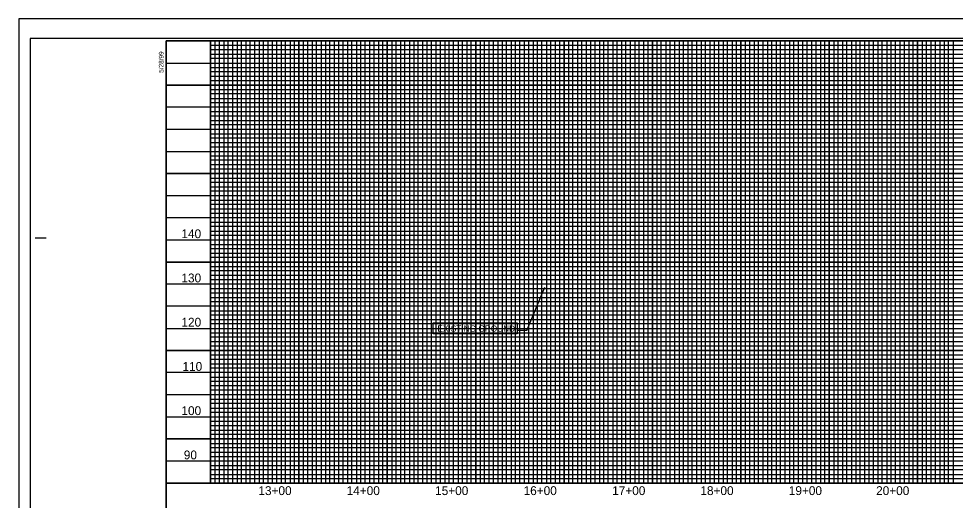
# Model space of a CAD drawing. Extents: x 10070 to 15319, y 8517 to 10343.
# Drawn here: x 13208 to 14267, y 9072 to 9617 of the extents above; entities that cross this region are included whole.
import ezdxf

# ---------------------------------------------------------------- set-up
doc = ezdxf.new("R2010")
doc.units = 0
for name, color, linetype in [('Exist Vertical Profile Horizontal Axis Label Major', 7, 'Continuous'), ('Exist Vertical Profile Vertical Axis Label', 7, 'Continuous'), ('Prop Grid Mask', 7, 'Continuous'), ('Prop VPI Label', 7, 'Continuous'), ('Scratch_Level_3', 7, 'Continuous'), ('Scratch_Level_4', 7, 'Continuous'), ('Sheet Cutting Line CELL', 7, 'Continuous'), ('Sheet DOT Grid CELL', 7, 'Continuous'), ('Sheet Layout Profile Border Port 1', 7, 'Continuous'), ('Sheet Plot Border Inside CELL', 7, 'Continuous'), ('Sheet Plot Border Outside CELL', 7, 'Continuous'), ('Sheet Profile CELL', 7, 'Continuous'), ('Sheet Profile Grid Major CELL', 7, 'Continuous'), ('Sheet Profile Grid Middle CELL', 7, 'Continuous'), ('Sheet Profile Grid Minor CELL', 7, 'Continuous')]:
    doc.layers.add(name, color=color, linetype=linetype)

msp = doc.modelspace()

# ---------------------------------------------------------------- linework, layer by layer
at = {"layer": 'Prop Grid Mask'}
msp.add_lwpolyline([(13676.8, 9260.7), (13676.8, 9272.9), (13772, 9272.9), (13772, 9260.7)], close=True, dxfattribs=at)
at = {"layer": 'Prop VPI Label'}
for q in [(13803.2, 9313.4), (13772, 9264.5)]:
    msp.add_line((13782.6, 9264.5), q, dxfattribs=at)
at = {"layer": 'Scratch_Level_3'}
msp.add_lwpolyline([(13374.9, 9591.7), (14824.9, 9591.7), (14824.9, 8566.7), (13374.9, 8566.7)], close=True, dxfattribs=at)
at = {"layer": 'Scratch_Level_4'}
msp.add_lwpolyline([(13374.9, 9591.7), (14874.9, 9591.7), (14874.9, 9091.7), (13374.9, 9091.7)], close=True, dxfattribs=at)
at = {"layer": 'Sheet Cutting Line CELL'}
for p, q in [((14891.9, 9616.7), (13207.9, 9616.7)), ((13207.9, 9616.7), (13207.9, 8516.7))]:
    msp.add_line(p, q, dxfattribs=at)
at = {"layer": 'Sheet DOT Grid CELL'}
for p, q in [((13424.9, 9091.7), (13424.9, 9591.7)), ((13474.9, 9091.7), (13474.9, 9591.7)), ((13524.9, 9091.7), (13524.9, 9591.7)), ((13574.9, 9091.7), (13574.9, 9591.7)), ((13624.9, 9091.7), (13624.9, 9591.7)), ((13674.9, 9091.7), (13674.9, 9591.7)), ((13724.9, 9091.7), (13724.9, 9591.7)), ((13774.9, 9091.7), (13774.9, 9591.7)), ((13824.9, 9091.7), (13824.9, 9591.7)), ((13874.9, 9091.7), (13874.9, 9591.7)), ((13924.9, 9091.7), (13924.9, 9591.7)), ((13974.9, 9091.7), (13974.9, 9591.7)), ((14024.9, 9091.7), (14024.9, 9591.7)), ((14074.9, 9091.7), (14074.9, 9591.7)), ((14124.9, 9091.7), (14124.9, 9591.7)), ((14174.9, 9091.7), (14174.9, 9591.7)), ((14224.9, 9091.7), (14224.9, 9591.7)), ((14674.9, 9541.7), (13374.9, 9541.7)), ((14674.9, 9491.7), (13374.9, 9491.7)), ((14674.9, 9441.7), (13374.9, 9441.7)), ((14874.9, 9391.7), (13374.9, 9391.7)), ((14874.9, 9341.7), (13374.9, 9341.7)), ((14874.9, 9291.7), (13374.9, 9291.7)), ((14874.9, 9241.7), (13374.9, 9241.7)), ((14874.9, 9191.7), (13374.9, 9191.7)), ((14874.9, 9141.7), (13374.9, 9141.7))]:
    msp.add_line(p, q, dxfattribs=at)
at = {"layer": 'Sheet Layout Profile Border Port 1'}
msp.add_lwpolyline([(13424.9, 9430.7), (13424.9, 9091.7), (14824.9, 9091.7), (14824.9, 9430.7)], dxfattribs=at)
at = {"layer": 'Sheet Plot Border Inside CELL'}
msp.add_lwpolyline([(13220.9, 8539.2), (14887.4, 8539.2), (14887.4, 9594.3), (13220.9, 9594.3)], close=True, dxfattribs=at)
at = {"layer": 'Sheet Plot Border Outside CELL'}
msp.add_lwpolyline([(13207.9, 8516.7), (14891.9, 8516.7), (14891.9, 9616.7), (13207.9, 9616.7)], close=True, dxfattribs=at)
at = {"layer": 'Sheet Profile CELL'}
for p, q in [((13226.4, 9369.2), (13238.9, 9369.2)), ((13374.9, 9091.7), (14874.9, 9091.7))]:
    msp.add_line(p, q, dxfattribs=at)
msp.add_lwpolyline([(14874.9, 9591.7), (13374.9, 9591.7), (13374.9, 8541.7), (14874.9, 8541.7)], close=True, dxfattribs=at)
at = {"layer": 'Sheet Profile Grid Major CELL'}
for points in [[(13424.9, 9591.7), (13424.9, 9091.7), (13474.9, 9091.7), (13474.9, 9591.7), (13524.9, 9591.7), (13524.9, 9091.7), (13574.9, 9091.7), (13574.9, 9591.7), (13624.9, 9591.7), (13624.9, 9091.7), (13674.9, 9091.7), (13674.9, 9591.7), (13724.9, 9591.7), (13724.9, 9091.7), (13774.9, 9091.7), (13774.9, 9591.7), (13824.9, 9591.7), (13824.9, 9091.7), (13874.9, 9091.7), (13874.9, 9591.7), (13924.9, 9591.7), (13924.9, 9091.7), (13974.9, 9091.7), (13974.9, 9591.7), (14024.9, 9591.7), (14024.9, 9091.7), (14074.9, 9091.7), (14074.9, 9591.7), (14124.9, 9591.7), (14124.9, 9091.7), (14174.9, 9091.7), (14174.9, 9591.7), (14224.9, 9591.7), (14224.9, 9091.7), (14274.9, 9091.7)], [(13374.9, 9541.7), (14674.9, 9541.7)], [(14674.9, 9491.7), (13374.9, 9491.7), (13374.9, 9441.7), (14674.9, 9441.7)], [(14874.9, 9391.7), (13374.9, 9391.7), (13374.9, 9341.7), (14874.9, 9341.7)], [(14874.9, 9291.7), (13374.9, 9291.7), (13374.9, 9241.7), (14874.9, 9241.7)], [(14874.9, 9191.7), (13374.9, 9191.7), (13374.9, 9191.7), (13374.9, 9141.7), (14874.9, 9141.7)]]:
    msp.add_lwpolyline(points, dxfattribs=at)
at = {"layer": 'Sheet Profile Grid Middle CELL'}
msp.add_line((13374.9, 9566.7), (14674.9, 9566.7), dxfattribs=at)
for points in [[(13449.9, 9591.7), (13449.9, 9091.7), (13499.9, 9091.7), (13499.9, 9591.7), (13549.9, 9591.7), (13549.9, 9091.7), (13599.9, 9091.7), (13599.9, 9591.7), (13649.9, 9591.7), (13649.9, 9091.7), (13699.9, 9091.7), (13699.9, 9591.7), (13749.9, 9591.7), (13749.9, 9091.7), (13799.9, 9091.7), (13799.9, 9591.7), (13849.9, 9591.7), (13849.9, 9091.7), (13899.9, 9091.7), (13899.9, 9591.7), (13949.9, 9591.7), (13949.9, 9091.7), (13999.9, 9091.7), (13999.9, 9091.7), (13999.9, 9591.7), (14049.9, 9591.7), (14049.9, 9091.7), (14099.9, 9091.7), (14099.9, 9591.7), (14149.9, 9591.7), (14149.9, 9091.7), (14199.9, 9091.7), (14199.9, 9591.7), (14249.9, 9591.7), (14249.9, 9091.7), (14299.9, 9091.7)], [(14674.9, 9516.7), (13374.9, 9516.7), (13374.9, 9466.7), (14674.9, 9466.7)], [(14874.9, 9416.7), (13374.9, 9416.7), (13374.9, 9366.7), (14699.9, 9366.7)], [(14874.9, 9316.7), (13374.9, 9316.7), (13374.9, 9266.7), (14874.9, 9266.7)], [(14874.9, 9216.7), (13374.9, 9216.7), (13374.9, 9166.7), (14874.9, 9166.7)], [(14874.9, 9116.7), (13374.9, 9116.7)]]:
    msp.add_lwpolyline(points, dxfattribs=at)
at = {"layer": 'Sheet Profile Grid Minor CELL'}
for p, q in [((13424.9, 9586.7), (14674.9, 9586.7)), ((13424.9, 9581.7), (13424.9, 9581.7)), ((14674.9, 9581.7), (13424.9, 9581.4)), ((13424.9, 9576.7), (14674.9, 9576.7)), ((14674.9, 9456.7), (13424.9, 9456.7)), ((14674.9, 9451.7), (13424.9, 9451.7)), ((14674.9, 9446.7), (13424.9, 9446.7)), ((13424.9, 9436.7), (14674.9, 9436.7)), ((14674.9, 9431.7), (13424.9, 9431.7)), ((13424.9, 9426.7), (14824.9, 9426.7)), ((14824.9, 9406.7), (13424.9, 9406.7)), ((13424.9, 9401.7), (14824.9, 9401.7)), ((14824.9, 9381.7), (13424.9, 9381.7)), ((13424.9, 9376.7), (14824.9, 9376.7)), ((14824.9, 9356.7), (13424.9, 9356.7)), ((13424.9, 9351.7), (14824.9, 9351.7)), ((14824.9, 9346.7), (13424.9, 9346.7)), ((13424.9, 9336.7), (14824.9, 9336.7)), ((14824.9, 9331.7), (13424.9, 9331.7)), ((13424.9, 9326.7), (14824.9, 9326.7)), ((14824.9, 9321.7), (13424.9, 9321.7)), ((13424.9, 9311.7), (14824.9, 9311.7)), ((14824.9, 9306.7), (13424.9, 9306.7)), ((13424.9, 9301.7), (14824.9, 9301.7)), ((14824.9, 9296.7), (13424.9, 9296.7)), ((13424.9, 9286.7), (14824.9, 9286.7)), ((14824.9, 9281.7), (13424.9, 9281.7)), ((13424.9, 9276.7), (14824.9, 9276.7)), ((14824.9, 9271.7), (13424.9, 9271.7)), ((13424.9, 9261.7), (14824.9, 9261.7)), ((14824.9, 9256.7), (13424.9, 9256.7)), ((13424.9, 9251.7), (14824.9, 9251.7)), ((14824.9, 9246.7), (13424.9, 9246.7)), ((13424.9, 9236.7), (14824.9, 9236.7)), ((14824.9, 9231.7), (13424.9, 9231.7)), ((13424.9, 9226.7), (14824.9, 9226.7)), ((14824.9, 9221.7), (13424.9, 9221.7)), ((13424.9, 9211.7), (14824.9, 9211.7)), ((14824.9, 9206.7), (13424.9, 9206.7)), ((14824.9, 9201.7), (13424.9, 9201.7)), ((14824.9, 9196.7), (13424.9, 9196.7)), ((13424.9, 9186.7), (14824.9, 9186.7)), ((14824.9, 9181.7), (13424.9, 9181.7)), ((13424.9, 9176.7), (14824.9, 9176.7)), ((14824.9, 9171.7), (13424.9, 9171.7)), ((13424.9, 9161.7), (14824.9, 9161.7)), ((14824.9, 9156.7), (13424.9, 9156.7)), ((13424.9, 9151.7), (14824.9, 9151.7)), ((14824.9, 9146.7), (13424.9, 9146.7)), ((13424.9, 9136.7), (14824.9, 9136.7)), ((14824.9, 9131.7), (13424.9, 9131.7)), ((13424.9, 9126.7), (14824.9, 9126.7)), ((14824.9, 9121.7), (13424.9, 9121.7)), ((13424.9, 9111.7), (14824.9, 9111.7)), ((14824.9, 9106.7), (13424.9, 9106.7)), ((13424.9, 9101.7), (14824.9, 9101.7))]:
    msp.add_line(p, q, dxfattribs=at)
for points in [[(13429.9, 9591.7), (13429.9, 9091.7), (13434.9, 9091.7), (13434.9, 9591.7), (13439.9, 9591.7), (13439.9, 9091.7), (13444.9, 9091.7), (13444.9, 9591.7), (13454.9, 9591.7), (13454.9, 9091.7), (13459.9, 9091.7), (13459.9, 9591.7), (13464.9, 9591.7), (13464.9, 9091.7), (13469.9, 9091.7), (13479.9, 9091.7), (13484.9, 9091.7), (13484.9, 9591.7), (13489.9, 9591.7), (13489.9, 9091.7), (13494.9, 9091.7), (13494.9, 9591.7), (13504.9, 9591.7), (13504.9, 9091.7), (13509.9, 9091.7), (13509.9, 9591.7), (13514.9, 9591.7), (13514.9, 9091.7), (13519.9, 9091.7), (13519.9, 9591.7), (13529.9, 9591.7), (13529.9, 9091.7), (13534.9, 9091.7), (13534.9, 9591.7), (13539.9, 9591.7), (13539.9, 9091.7), (13544.9, 9091.7), (13544.9, 9591.7), (13554.9, 9591.7), (13554.9, 9091.7), (13559.9, 9091.7), (13559.9, 9591.7), (13564.9, 9591.7), (13564.9, 9091.7), (13569.9, 9091.7), (13569.9, 9591.7), (13579.9, 9591.7), (13579.9, 9091.7), (13584.9, 9091.7), (13584.9, 9591.7), (13589.9, 9591.7), (13589.9, 9091.7), (13594.9, 9091.7), (13594.9, 9591.7), (13604.9, 9591.7), (13604.9, 9091.7), (13609.9, 9091.7), (13609.9, 9591.7), (13614.9, 9591.7), (13614.9, 9091.7), (13619.9, 9091.7), (13619.9, 9591.7), (13629.9, 9591.7), (13629.9, 9091.7), (13634.9, 9091.7), (13634.9, 9591.7), (13639.9, 9591.7), (13639.9, 9091.7)], [(13469.9, 9091.7), (13469.9, 9591.7), (13479.9, 9591.7), (13479.9, 9091.7)], [(13639.9, 9091.7), (13644.9, 9091.7), (13644.9, 9591.7), (13654.9, 9591.7), (13654.9, 9091.7), (13659.9, 9091.7), (13659.9, 9591.7), (13664.9, 9591.7), (13664.9, 9091.7), (13669.9, 9091.7), (13669.9, 9591.7), (13679.9, 9591.7), (13679.9, 9091.7), (13684.9, 9091.7), (13684.9, 9591.7), (13689.9, 9591.7), (13689.9, 9091.7), (13694.9, 9091.7), (13694.9, 9591.7), (13704.9, 9591.7), (13704.9, 9091.7), (13709.9, 9091.7), (13709.9, 9591.7), (13714.9, 9591.7), (13714.9, 9091.7), (13719.9, 9091.7), (13719.9, 9591.7), (13729.9, 9591.7), (13729.9, 9091.7), (13734.9, 9091.7), (13734.9, 9591.7), (13739.9, 9591.7), (13739.9, 9091.7), (13744.9, 9091.7), (13744.9, 9591.7), (13754.9, 9591.7), (13754.9, 9091.7), (13759.9, 9091.7), (13759.9, 9591.7), (13764.9, 9591.7), (13764.9, 9091.7), (13769.9, 9091.7), (13769.9, 9591.7), (13779.9, 9591.7), (13779.9, 9091.7), (13784.9, 9091.7), (13784.9, 9591.7), (13789.9, 9591.7), (13789.9, 9091.7), (13794.9, 9091.7), (13794.9, 9591.7), (13804.9, 9591.7), (13804.9, 9091.7), (13809.9, 9091.7), (13809.9, 9591.7), (13814.9, 9591.7), (13814.9, 9091.7), (13819.9, 9091.7), (13819.9, 9591.7), (13829.9, 9591.7), (13829.9, 9091.7), (13834.9, 9091.7), (13834.9, 9591.7), (13839.9, 9591.7), (13839.9, 9091.7), (13844.9, 9091.7), (13844.9, 9591.7), (13854.9, 9591.7), (13854.9, 9091.7), (13859.9, 9091.7), (13859.9, 9591.7), (13864.9, 9591.7), (13864.9, 9091.7), (13869.9, 9091.7), (13869.9, 9591.7), (13879.9, 9591.7), (13879.9, 9091.7), (13884.9, 9091.7), (13884.9, 9591.7), (13889.9, 9591.7), (13889.9, 9091.7), (13894.9, 9091.7), (13894.9, 9591.7), (13904.9, 9591.7), (13904.9, 9091.7), (13909.9, 9091.7), (13909.9, 9591.7), (13914.9, 9591.7), (13914.9, 9091.7), (13919.9, 9091.7), (13919.9, 9591.7), (13929.9, 9591.7), (13929.9, 9091.7), (13934.9, 9091.7), (13934.9, 9591.7), (13939.9, 9591.7), (13939.9, 9091.7), (13944.9, 9091.7), (13944.9, 9591.7), (13954.9, 9591.7)], [(13954.9, 9591.7), (13954.9, 9091.7), (13959.9, 9091.7), (13959.9, 9591.7), (13964.9, 9591.7), (13964.9, 9091.7), (13969.9, 9091.7), (13969.9, 9591.7), (13979.9, 9591.7), (13979.9, 9091.7), (13984.9, 9091.7), (13984.9, 9591.7), (13989.9, 9591.7), (13989.9, 9091.7), (13994.9, 9091.7), (13994.9, 9591.7), (14004.9, 9591.7), (14004.9, 9091.7), (14009.9, 9091.7), (14009.9, 9591.7), (14014.9, 9591.7), (14014.9, 9091.7), (14019.9, 9091.7), (14019.9, 9591.7), (14029.9, 9591.7), (14029.9, 9091.7), (14034.9, 9091.7), (14034.9, 9591.7), (14039.9, 9591.7), (14039.9, 9091.7), (14044.9, 9091.7), (14044.9, 9591.7), (14054.9, 9591.7), (14054.9, 9091.7), (14059.9, 9091.7), (14059.9, 9591.7), (14064.9, 9591.7), (14064.9, 9091.7), (14069.9, 9091.7), (14069.9, 9591.7), (14079.9, 9591.7), (14079.9, 9091.7), (14079.9, 9091.7), (14084.9, 9091.7), (14084.9, 9591.7), (14089.9, 9591.7), (14089.9, 9091.7), (14094.9, 9091.7), (14094.9, 9591.7), (14104.9, 9591.7), (14104.9, 9091.7), (14109.9, 9091.7), (14109.9, 9591.7), (14114.9, 9591.7), (14114.9, 9091.7), (14119.9, 9091.7), (14119.9, 9591.7), (14129.9, 9591.7), (14129.9, 9091.7), (14134.9, 9091.7), (14134.9, 9591.7), (14139.9, 9591.7), (14139.9, 9091.7), (14144.9, 9091.7), (14144.9, 9591.7), (14154.9, 9591.7), (14154.9, 9091.7), (14159.9, 9091.7), (14159.9, 9591.7), (14164.9, 9591.7), (14164.9, 9091.7), (14169.9, 9091.7), (14169.9, 9591.7), (14179.9, 9591.7), (14179.9, 9091.7), (14184.9, 9091.7), (14184.9, 9591.7), (14189.9, 9591.7), (14189.9, 9091.7), (14194.9, 9091.7), (14194.9, 9591.7), (14204.9, 9591.7), (14204.9, 9091.7), (14209.9, 9091.7), (14209.9, 9591.7), (14214.9, 9591.7), (14214.9, 9091.7), (14219.9, 9091.7), (14219.9, 9591.7), (14229.9, 9591.7), (14229.9, 9091.7), (14234.6, 9092.3), (14234.9, 9091.7), (14234.9, 9591.7), (14239.9, 9591.7), (14239.9, 9091.7), (14244.9, 9091.7), (14244.9, 9591.7), (14254.9, 9591.7), (14254.9, 9091.7), (14259.9, 9091.7)], [(14259.9, 9091.7), (14259.9, 9591.7), (14264.9, 9591.7), (14264.9, 9091.7), (14269.9, 9091.7)], [(14674.9, 9571.7), (13424.9, 9571.7), (13424.9, 9561.7), (14674.9, 9561.7)], [(14674.9, 9556.7), (13424.9, 9556.7), (13424.9, 9551.7), (14674.9, 9551.7)], [(14674.9, 9546.7), (13424.9, 9546.7), (13424.9, 9536.7), (14674.9, 9536.7)], [(14674.9, 9531.7), (13424.9, 9531.7), (13424.9, 9526.7), (14674.9, 9526.7)], [(14674.9, 9521.7), (13424.9, 9521.7), (13424.9, 9511.7), (14674.9, 9511.7)], [(14674.9, 9506.7), (13424.9, 9506.7), (13424.9, 9501.7), (14674.9, 9501.7)], [(14674.9, 9496.7), (13424.9, 9496.7), (13424.9, 9486.7), (14674.9, 9486.7)], [(14674.9, 9481.6), (13425, 9481.6), (13425, 9476.7), (14674.9, 9476.7)], [(14674.9, 9471.7), (13424.9, 9471.7), (13424.9, 9461.7), (14674.9, 9461.7)], [(14824.9, 9421.7), (13424.9, 9421.7), (13424.9, 9411.7), (14824.9, 9411.7)], [(14824.9, 9396.7), (13424.9, 9396.7), (13424.9, 9386.7), (14824.9, 9386.7)], [(14824.9, 9371.7), (13424.9, 9371.7), (13424.9, 9361.7), (14824.9, 9361.7)], [(14824.9, 9096.7), (13424.9, 9096.7)]]:
    msp.add_lwpolyline(points, dxfattribs=at)

# ---------------------------------------------------------------- texts
at = {"layer": 'Exist Vertical Profile Horizontal Axis Label Major'}
for s, p in [('13+00', (13479.1, 9078.3)), ('14+00', (13578.9, 9078.3)), ('15+00', (13679, 9078.3)), ('16+00', (13779.1, 9078.3)), ('17+00', (13879.3, 9078.3)), ('18+00', (13979.1, 9078.3)), ('19+00', (14079.1, 9078.3)), ('20+00', (14177.9, 9078.3))]:
    msp.add_text(s, height=10, dxfattribs=at).set_placement(p)
at = {"layer": 'Exist Vertical Profile Vertical Axis Label'}
for s, p in [('140', (13392, 9368.7)), ('130', (13392, 9318.7)), ('120', (13392, 9268.7)), ('110', (13393.2, 9218.7)), ('100', (13392, 9168.7)), ('90', (13394.7, 9118.7))]:
    msp.add_text(s, height=10, dxfattribs=at).set_placement(p)
at = {"layer": 'Prop VPI Label'}
msp.add_text('EXISTING GROUND', height=7, rotation=360, dxfattribs=at).set_placement((13681.6, 9263))
at = {"layer": 'Sheet Profile CELL'}
msp.add_text('5/28/99', height=5.25, rotation=90, dxfattribs=at).set_placement((13371.7, 9555.6))

doc.saveas('drawing.dxf')
